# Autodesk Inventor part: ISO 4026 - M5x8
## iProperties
Author: Philippe
Created: 2001-12
Part Number: ISO 4026 - M5x8
Material: Par défaut
Catalog Web Link: file:///C:/Program Files/Autodesk/Inventor 5/Content/Iso/index.htm?doNavigateId=F1AA6529-0F56-4ECF-BA62-A9484B5C09E1|A6AC5A62BA3048DA9F089E18BCB56736|true
Description: Vis sans tête à six pans creux
Document SubType Name: Standard Catalog Part
Standard: ISO 4026 - M5x8
Designer: Philippe
CLASSIFICATION: 31161505 un/spsc
MANUFACTURER: ISO Système de normes
Control State: 0
Master: False
Checked Out: False
PropertySet Name: Design Tracking Control
Shininess: 20.0
Angle Display Precision: 2
Document Length Units: 11269
Document Angle Units: 11283
Document Time Units: 11279
Document Mass Units: 11290
Document Length Units Precision: 3
Document Angle Units Precision: 2
Compacted: False
PropertySet Name: _Private Model Information
Density: 0.0
Volumn: 0.0
Area: 0.0
PropertySet Name: Model Information
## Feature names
1. Base1
